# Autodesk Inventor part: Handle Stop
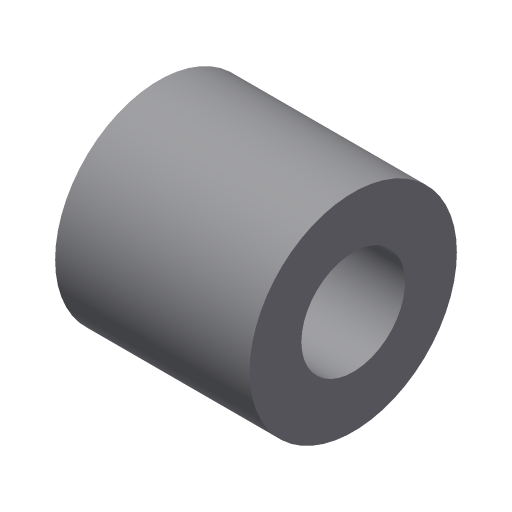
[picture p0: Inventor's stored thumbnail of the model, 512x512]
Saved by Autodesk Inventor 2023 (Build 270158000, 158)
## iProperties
Created: 2002-02
Part Number: Handle Stop
Document SubType Name: Modeling
Designer: ***
Density: 1 g/cm^3
Material: Generic
Appearance: Default
Control State: 0
Master: False
Checked Out: False
Shininess: 77.0
Length Units: 11269
Angle Units: 11279
Time Units: 11290
Mass Units: 11283
Length Display Precision: 3
Angle Display Precision: 2
Compacted: True
Density: 0.0
Volumn: 0.0
Area: 0.0
PropertySet Name: Model Information
Author: ***
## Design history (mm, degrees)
sketch "Sketch1"
  geometry: L1 (0, 0)-(0, -2); L2 (0, -2)-(8, -2); L3 (8, -2)-(8, 13); L4 (8, 13)-(4, 13); L5 (4, 13)-(4, 0); L6 (4, 0)-(0, 0)
  constraints: 12 end point, 4 parallel, 1 perpendicular, 1 vertical
  dimensions: "d0" = 16 diameter of L3 L1; "d1" = 8 diameter of L5 L1; "d2" = 2 distance of L1.start L1.end; "d3" = 15 distance of L2.end L3.end
revolve "Revolution1" sketch "Sketch1" stored, may be unused: angle "d4" = 90 deg
body "Solid1"
